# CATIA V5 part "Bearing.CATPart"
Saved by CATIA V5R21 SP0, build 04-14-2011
Part number: Part1
Material "Steel": density 7860 kg/m3, Young's modulus 2e+11 Pa, Poisson ratio 0.266, thermal expansion 1.17e-05 1/K
Bounding box of the stored display mesh (mm): x -5.75 to 5.75, y -5.74 to 5.74, z 0 to 5
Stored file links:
  G:\CATIA\Universial Joint\Bearing.CATPart
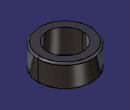
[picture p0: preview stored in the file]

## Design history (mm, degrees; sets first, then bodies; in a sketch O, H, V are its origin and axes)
Body1 (main body), material "Steel"
  Sketch1 on xy-plane, origin (0, 0, 0), H (1, 0, 0), V (0, 1, 0)
    circle A1 centre (0, 0) radius 5.75
    circle A2 centre (0, 0) radius 3.75
    radius A1 = 5.75
    radius A2 = 3.75
  Pad1: profile Sketch1, direction (0, 0, 1), length 5
  Fillet1: radius 0.4, on edge [face of Pad1 from Sketch1.A1 | end face of Pad1]; edge [start face of Pad1 | face of Pad1 from Sketch1.A1]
